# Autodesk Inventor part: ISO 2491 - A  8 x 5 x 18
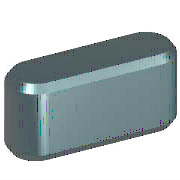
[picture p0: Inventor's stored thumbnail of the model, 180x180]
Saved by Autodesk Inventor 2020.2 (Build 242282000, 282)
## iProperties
IsCustomPart: 0
Manager: www.cadconsulting.pl
Company: Fabian Stasiak CAD Consulting
Created: 2010-02
Part Number: ISO 2491 - A  8 x 5 x 18
Material: Stal, miękka
Description: Wpusty pryzmatyczne cienkie
Document SubType Name: Modeling
Standard: ISO 2491
Designer: F.Stasiak
Standard Revision: First edition 1974-08-15
Standards Organization: ISO
Language: pl-PL
Size Designation: A  8 x 5 x 18
Categories: <MemberInstance><Categories><Category DisplayName="Części wałów" InternalName="7f7aeb1f-a693-4053-b835-cee3144e0d98" Mnemonic="SHFT"><Category DisplayName="Klin
Density: 1 g/cm^3
Appearance: Metal-Stal
Author: F.Stasiak
Subject: Zbiór ćwiczeń. Autodesk Inventor 2020. Kurs podstawowy
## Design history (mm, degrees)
sketch "Sketch1"
  geometry: L1 (4, 4)-(14, 4); L2 (14, -4)-(4, -4); L3 (0, 9.4)-(0, -7.4) reference; L4 (-5, 0)-(30, 0) reference; L5 (18, 0)-(18, 7); A1 r 4 centre (4, 0) between (4, 4) and (4, -4); A2 r 4 centre (14, 0) between (14, -4) and (14, 4)
  constraints: 6 end point, 5 point on circle, 4 tangent, 3 point on line, 2 centre point, 1 horizontal, 1 parallel, 1 perpendicular
  dimensions: "d0" = 4 radius of A1 (= 0.5 x PB); "d13" = 4 radius of A2 (= 0.5 x PB); "d14" = 18 distance between parallel lines of L5 L3 (= NLG)
workplane "Work Plane1"
workplane "Work Plane2"
extrude "Body1" new body sketch "Sketch1" taper "d3" = 0 deg; stored distance "d4" = 10
chamfer "Chamfer1" distance "d8" = 0.4 (= PHH); stored, may be unused: second distance "d9" = 0.4 (= PHH), angle "d15" = 45 deg
workplane "Work Plane3"
body "Solid1"
other parameters: "d1" = -3 (= -PNT), "d2" = 2 (= PH - PNT), "NLG" = 18 [user parameter; used in 1 equation term], "PB" = 8 [user parameter; used in 2 equation terms], "PNT" = 3 [user parameter; used in 2 equation terms], "PH" = 5 [user parameter; used in 1 equation term], "PHH" = 0.4 [user parameter; used in 2 equation terms], "d10" = 0, "d16" = 0, "d17" = 0, "d18" = 0, "RR" = 0.16 [user parameter], "WDMIN" = 22 [user parameter], "PLB1" = 18 [user parameter], "PLB2" = 18 [user parameter], "PUEB" = 2.3 [user parameter]
